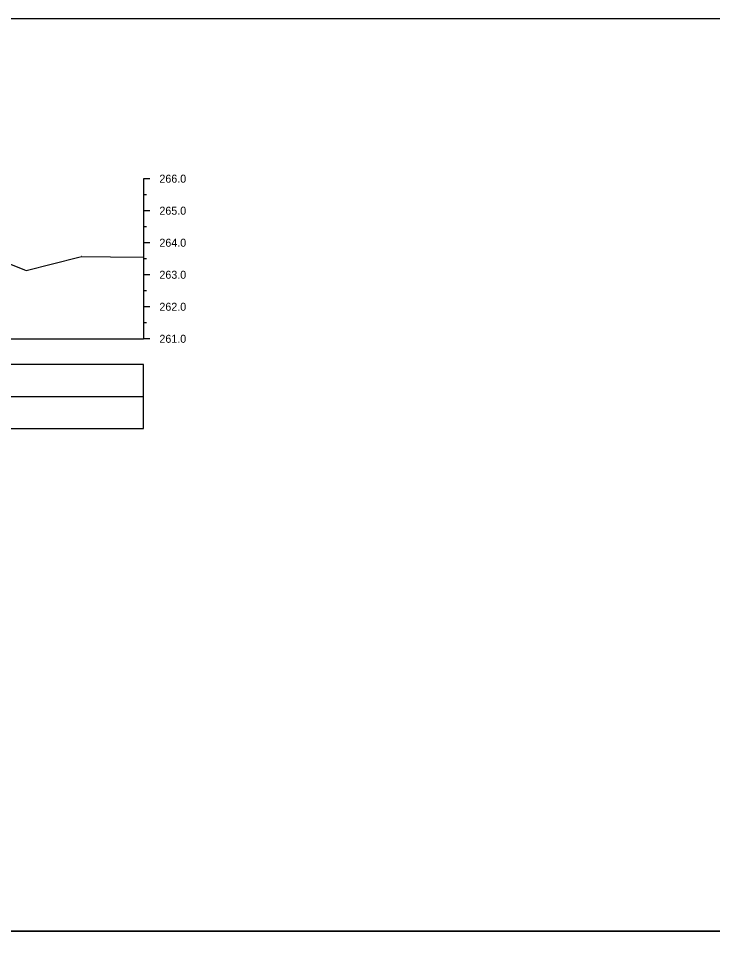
# Model space of a CAD drawing. Extents: x -1 to 65640748, y -22 to 5530284.
# Drawn here: x 2509.43 to 2531.1, y 994.37 to 1023.44 of the extents above; entities that cross this region are included whole.
import ezdxf

# ---------------------------------------------------------------- set-up
doc = ezdxf.new("R2010")
doc.units = 0
for name, color, linetype in [('IR_cross_section', 7, 'Continuous'), ('IR_default', 7, 'Continuous'), ('TOR_PRZEK_P-tabelka projektowane', 7, 'Continuous'), ('TOR_PRZEK_P-teren istniejacy', 7, 'Continuous'), ('TOR_PRZEK_P-uklad odniesienia', 7, 'Continuous')]:
    doc.layers.add(name, color=color, linetype=linetype)

msp = doc.modelspace()

# ---------------------------------------------------------------- linework, layer by layer
at = {"layer": 'IR_cross_section'}
for points in [[(2476.328, 1023.438), (2676.328, 1023.438), (2676.328, 994.938), (2476.328, 994.938)], [(2476.328, 994.938), (2676.328, 994.938), (2676.328, 966.438), (2476.328, 966.438)]]:
    msp.add_lwpolyline(points, close=True, dxfattribs=at)
at = {"layer": 'IR_default'}
for points in [[(2511.401, 1016.009), (2511.4, 1016.009), (2511.401, 1016.009), (2511.4, 1016.008), (2511.401, 1016.009), (2511.401, 1016.008), (2511.401, 1016.009), (2511.401, 1016.009)], [(2509.67, 1015.568), (2509.669, 1015.568), (2509.67, 1015.568), (2509.669, 1015.567), (2509.67, 1015.568), (2509.67, 1015.567), (2509.67, 1015.568), (2509.67, 1015.568)]]:
    msp.add_lwpolyline(points, dxfattribs=at)
at = {"layer": 'TOR_PRZEK_P-tabelka projektowane'}
msp.add_line((2479.528, 1011.638), (2513.328, 1011.638), dxfattribs=at)
msp.add_lwpolyline([(2479.528, 1012.638), (2479.528, 1010.638), (2513.328, 1010.638), (2513.328, 1012.638)], close=True, dxfattribs=at)
at = {"layer": 'TOR_PRZEK_P-teren istniejacy'}
msp.add_lwpolyline([(2508.974, 1015.851), (2509.616, 1015.59), (2509.67, 1015.568), (2511.312, 1015.983), (2511.401, 1016.009), (2512.296, 1016), (2513.328, 1015.985)], dxfattribs=at)
at = {"layer": 'TOR_PRZEK_P-uklad odniesienia'}
for p, q in [((2513.328, 1018.438), (2513.328, 1013.438)), ((2513.528, 1018.438), (2513.328, 1018.438)), ((2513.428, 1017.938), (2513.328, 1017.938)), ((2513.528, 1017.438), (2513.328, 1017.438)), ((2513.428, 1016.938), (2513.328, 1016.938)), ((2513.528, 1016.438), (2513.328, 1016.438)), ((2513.428, 1015.938), (2513.328, 1015.938)), ((2513.528, 1015.438), (2513.328, 1015.438)), ((2513.428, 1014.938), (2513.328, 1014.938)), ((2513.528, 1014.438), (2513.328, 1014.438)), ((2513.428, 1013.938), (2513.328, 1013.938)), ((2483.328, 1013.438), (2513.328, 1013.438)), ((2513.528, 1013.438), (2513.328, 1013.438))]:
    msp.add_line(p, q, dxfattribs=at)

# ---------------------------------------------------------------- texts
for s, p in [('266.0', (2513.828, 1018.313)), ('265.0', (2513.828, 1017.313)), ('264.0', (2513.828, 1016.313)), ('263.0', (2513.828, 1015.313)), ('262.0', (2513.828, 1014.313)), ('261.0', (2513.828, 1013.313))]:
    msp.add_text(s, height=0.25, dxfattribs=at).set_placement(p)

doc.saveas('drawing.dxf')
